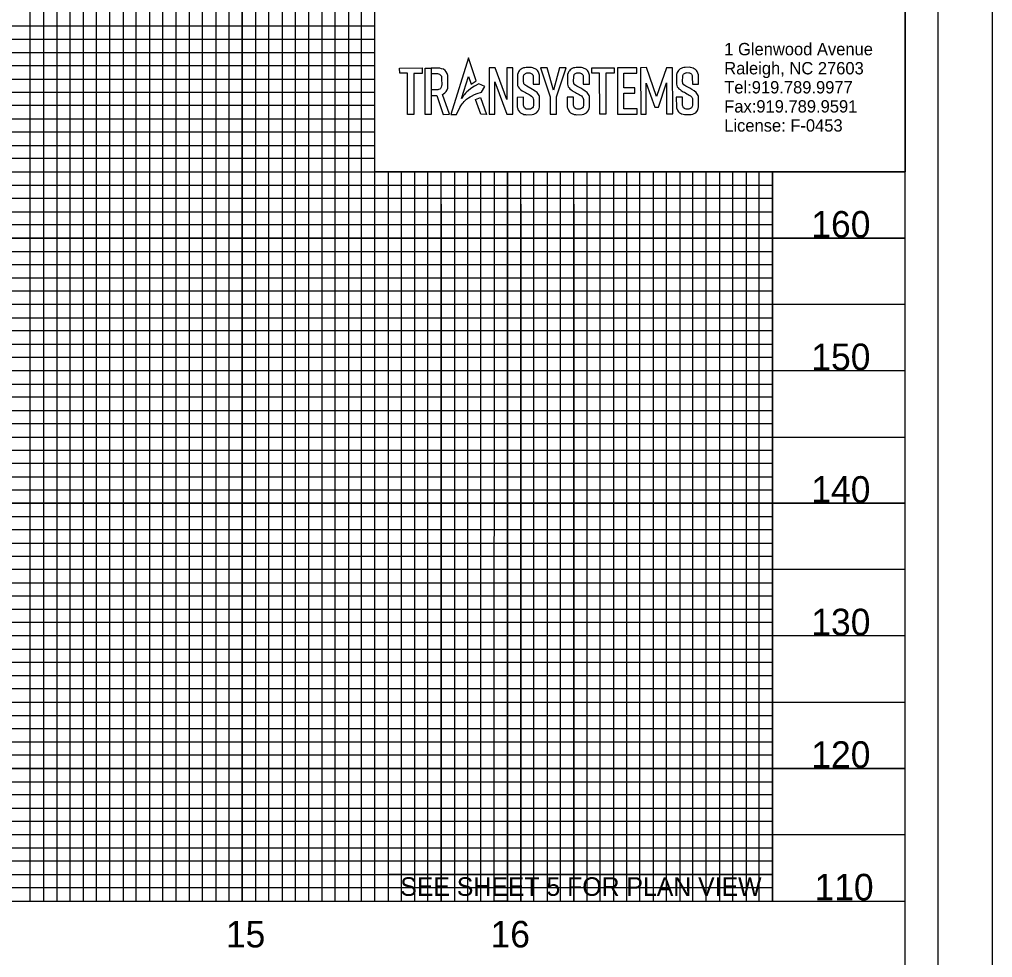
# Model space of a CAD drawing. Extents: x 1779926 to 1781626, y 618464 to 619564.
# Drawn here: x 1781258.9 to 1781626, y 619017.9 to 619371.7 of the extents above; entities that cross this region are included whole.
import ezdxf

# ---------------------------------------------------------------- set-up
doc = ezdxf.new("R2010")
doc.units = 0
for name, color, linetype in [('Default', 7, 'Continuous'), ('Exist Vertical Profile Horizontal Axis Label Major', 7, 'Continuous'), ('Exist Vertical Profile Vertical Axis Label', 7, 'Continuous'), ('Old_Level_2', 7, 'Continuous'), ('Old_Level_58', 7, 'Continuous'), ('Prop DSN Text', 7, 'Continuous'), ('Prop Grid Mask', 7, 'Continuous'), ('Sheet DOT Grid CELL', 7, 'Continuous'), ('Sheet Layout Profile Border Port 1', 7, 'Continuous'), ('Sheet Plot Border Inside CELL', 7, 'Continuous'), ('Sheet Plot Border Outside CELL', 7, 'Continuous'), ('Sheet Profile CELL', 7, 'Continuous'), ('Sheet Profile Grid Major CELL', 7, 'Continuous'), ('Sheet Profile Grid Middle CELL', 7, 'Continuous'), ('Sheet Profile Grid Minor CELL', 7, 'Continuous')]:
    doc.layers.add(name, color=color, linetype=linetype)

msp = doc.modelspace()

# ---------------------------------------------------------------- linework, layer by layer
at = {"layer": 'Default'}
for points in [[(1781428.25, 619357.23), (1781421.58, 619335.89), (1781423.81, 619335.9), (1781424.15, 619336.74), (1781424.72, 619337.9), (1781425.03, 619338.53), (1781425.41, 619339.07), (1781425.93, 619339.83), (1781426.26, 619340.3), (1781426.64, 619340.69), (1781427.02, 619341.08), (1781427.51, 619341.58), (1781427.92, 619341.85), (1781428.33, 619342.18), (1781428.89, 619342.5), (1781429.38, 619342.78), (1781430.6, 619343.35), (1781431.6, 619343.76), (1781433.24, 619344.32), (1781434.38, 619346.46), (1781432.2, 619347.42), (1781430.57, 619346.53), (1781429.19, 619345.63), (1781428.21, 619344.83), (1781427.69, 619344.41), (1781427.15, 619343.84), (1781426.62, 619343.27), (1781426.22, 619342.85), (1781425.84, 619342.2), (1781425.63, 619341.84), (1781428.26, 619350.22), (1781429.26, 619347.33), (1781431.16, 619348.58)], [(1781402.29, 619353.38), (1781410.75, 619353.39), (1781410.75, 619351.31), (1781407.64, 619351.31), (1781407.66, 619335.89), (1781405.31, 619335.89), (1781405.29, 619351.41), (1781402.32, 619351.41)], [(1781411.91, 619353.37), (1781414.22, 619353.38), (1781414.24, 619335.81), (1781411.92, 619335.81)], [(1781414.22, 619351.29), (1781416.61, 619351.29), (1781416.91, 619351.24), (1781417.32, 619351.08), (1781417.64, 619350.86), (1781417.87, 619350.59), (1781418.03, 619350.26), (1781418.15, 619350), (1781418.15, 619349.42), (1781418.16, 619346.93), (1781418.1, 619346.6), (1781418.01, 619346.16), (1781417.88, 619345.86), (1781417.68, 619345.6), (1781417.41, 619345.39), (1781416.99, 619345.24), (1781416.66, 619345.2), (1781416.34, 619345.15), (1781414.23, 619345.14), (1781414.24, 619343.03), (1781416.35, 619343.05), (1781418.72, 619335.88), (1781421.13, 619335.91), (1781418.48, 619343.45), (1781418.86, 619343.58), (1781419.4, 619343.98), (1781419.89, 619344.52), (1781420.23, 619345.15), (1781420.45, 619345.78), (1781420.43, 619345.97), (1781420.48, 619350.53), (1781420.27, 619351.28), (1781419.91, 619351.96), (1781419.5, 619352.43), (1781418.8, 619352.9), (1781418.12, 619353.13), (1781417.45, 619353.35), (1781417.04, 619353.35), (1781414.22, 619353.38)], [(1781436.02, 619353.41), (1781436.03, 619335.95), (1781438.27, 619335.95), (1781438.26, 619348.23), (1781442.71, 619335.93), (1781444.96, 619335.96), (1781444.94, 619353.46), (1781442.76, 619353.46), (1781442.78, 619341.48), (1781438.37, 619353.42)], [(1781452.72, 619347.24), (1781455.03, 619347.24), (1781455.02, 619350.72), (1781454.83, 619351.42), (1781454.55, 619352.01), (1781454.25, 619352.4), (1781453.88, 619352.76), (1781453.44, 619353.04), (1781453.01, 619353.21), (1781453.01, 619353.21), (1781452.55, 619353.41), (1781452.07, 619353.53), (1781451.75, 619353.61), (1781450, 619353.57), (1781449.47, 619353.48), (1781449.02, 619353.4), (1781448.55, 619353.16), (1781448.15, 619352.95), (1781447.76, 619352.67), (1781447.45, 619352.35), (1781447.2, 619351.99), (1781447.01, 619351.59), (1781446.75, 619350.9), (1781446.7, 619350.38), (1781446.7, 619347.21), (1781446.82, 619346.74), (1781447.05, 619346.24), (1781447.34, 619345.83), (1781447.63, 619345.52), (1781448.08, 619345.17), (1781448.54, 619344.83), (1781448.82, 619344.61), (1781449.3, 619344.38), (1781449.79, 619344.16), (1781450.18, 619343.9), (1781450.62, 619343.62), (1781451.15, 619343.35), (1781451.58, 619343.13), (1781452.01, 619342.82), (1781452.32, 619342.52), (1781452.57, 619342.28), (1781452.72, 619341.8), (1781452.82, 619341.5), (1781452.78, 619339.27), (1781452.62, 619338.78), (1781452.38, 619338.36), (1781452.05, 619338.07), (1781451.69, 619337.91), (1781451.35, 619337.84), (1781450.39, 619337.82), (1781450.07, 619337.91), (1781449.74, 619338.1), (1781449.41, 619338.3), (1781449.27, 619338.63), (1781449.13, 619338.97), (1781449.01, 619339.23), (1781448.98, 619342.35), (1781446.64, 619342.32), (1781446.68, 619338.61), (1781446.8, 619338.33), (1781447.07, 619337.46), (1781447.24, 619337.17), (1781447.5, 619336.85), (1781447.88, 619336.48), (1781448.18, 619336.29), (1781448.62, 619336.1), (1781448.78, 619336.04), (1781449.2, 619335.86), (1781449.74, 619335.8), (1781450.13, 619335.76), (1781452.27, 619335.82), (1781452.87, 619335.96), (1781453.69, 619336.33), (1781453.97, 619336.46), (1781454.6, 619337.25), (1781454.93, 619338.04), (1781455.08, 619338.75), (1781455.03, 619342.17), (1781455.02, 619342.64), (1781454.89, 619343.02), (1781454.7, 619343.37), (1781454.16, 619344.13), (1781453.45, 619344.69), (1781452.48, 619345.27), (1781451.73, 619345.71), (1781450.27, 619346.48), (1781449.52, 619347.04), (1781449.19, 619347.46), (1781449.11, 619347.74), (1781449.03, 619348.03), (1781449.08, 619350.46), (1781449.2, 619350.71), (1781449.33, 619350.97), (1781449.51, 619351.12), (1781449.74, 619351.32), (1781450, 619351.42), (1781450.25, 619351.53), (1781450.4, 619351.5), (1781450.42, 619351.58), (1781451.38, 619351.56), (1781451.65, 619351.45), (1781451.93, 619351.34), (1781452.21, 619351.23), (1781452.34, 619351.04), (1781452.52, 619350.76), (1781452.61, 619350.48), (1781452.71, 619350.21), (1781452.7, 619349.9)], [(1781457.99, 619353.42), (1781455.45, 619353.42), (1781459.07, 619342.54), (1781459.1, 619335.99), (1781461.49, 619336.01), (1781461.46, 619342.5), (1781465.12, 619353.46), (1781462.62, 619353.39), (1781460.31, 619345.05)], [(1781471.59, 619347.26), (1781473.9, 619347.26), (1781473.89, 619350.74), (1781473.7, 619351.44), (1781473.42, 619352.03), (1781473.12, 619352.42), (1781472.75, 619352.77), (1781472.31, 619353.06), (1781471.88, 619353.23), (1781471.88, 619353.23), (1781471.43, 619353.42), (1781470.94, 619353.55), (1781470.62, 619353.63), (1781468.87, 619353.59), (1781468.34, 619353.5), (1781467.89, 619353.42), (1781467.43, 619353.18), (1781467.02, 619352.97), (1781466.63, 619352.68), (1781466.32, 619352.37), (1781466.08, 619352.01), (1781465.88, 619351.61), (1781465.63, 619350.91), (1781465.58, 619350.4), (1781465.58, 619347.23), (1781465.69, 619346.75), (1781465.92, 619346.26), (1781466.21, 619345.85), (1781466.51, 619345.54), (1781466.96, 619345.19), (1781467.41, 619344.84), (1781467.69, 619344.62), (1781468.18, 619344.4), (1781468.66, 619344.17), (1781469.05, 619343.92), (1781469.49, 619343.63), (1781470.02, 619343.37), (1781470.45, 619343.15), (1781470.88, 619342.83), (1781471.19, 619342.54), (1781471.44, 619342.3), (1781471.59, 619341.82), (1781471.69, 619341.52), (1781471.65, 619339.28), (1781471.49, 619338.8), (1781471.25, 619338.38), (1781470.92, 619338.09), (1781470.56, 619337.93), (1781470.22, 619337.86), (1781469.26, 619337.84), (1781468.94, 619337.93), (1781468.61, 619338.12), (1781468.28, 619338.31), (1781468.14, 619338.65), (1781468, 619338.98), (1781467.88, 619339.25), (1781467.85, 619342.36), (1781465.51, 619342.34), (1781465.55, 619338.63), (1781465.67, 619338.34), (1781465.94, 619337.48), (1781466.12, 619337.19), (1781466.37, 619336.87), (1781466.75, 619336.5), (1781467.05, 619336.3), (1781467.49, 619336.12), (1781467.65, 619336.05), (1781468.08, 619335.87), (1781468.61, 619335.82), (1781469, 619335.78), (1781471.15, 619335.84), (1781471.74, 619335.98), (1781472.57, 619336.35), (1781472.85, 619336.48), (1781473.47, 619337.27), (1781473.8, 619338.05), (1781473.96, 619338.76), (1781473.9, 619342.19), (1781473.9, 619342.66), (1781473.76, 619343.03), (1781473.57, 619343.39), (1781473.03, 619344.15), (1781472.33, 619344.7), (1781471.35, 619345.28), (1781470.61, 619345.73), (1781469.14, 619346.49), (1781468.39, 619347.06), (1781468.06, 619347.48), (1781467.98, 619347.76), (1781467.91, 619348.05), (1781467.95, 619350.48), (1781468.08, 619350.73), (1781468.2, 619350.99), (1781468.38, 619351.14), (1781468.61, 619351.33), (1781468.87, 619351.44), (1781469.13, 619351.55), (1781469.27, 619351.52), (1781469.29, 619351.59), (1781470.25, 619351.58), (1781470.52, 619351.47), (1781470.8, 619351.36), (1781471.08, 619351.25), (1781471.21, 619351.06), (1781471.39, 619350.78), (1781471.49, 619350.5), (1781471.58, 619350.23), (1781471.57, 619349.92)], [(1781474.74, 619353.45), (1781483.21, 619353.45), (1781483.21, 619351.38), (1781480.1, 619351.38), (1781480.12, 619335.96), (1781477.77, 619335.95), (1781477.75, 619351.48), (1781474.78, 619351.48)], [(1781491.82, 619353.45), (1781484.43, 619353.45), (1781484.45, 619336.02), (1781491.92, 619336.03), (1781491.92, 619338), (1781486.87, 619337.99), (1781486.87, 619343.84), (1781491.08, 619343.84), (1781491.08, 619345.91), (1781486.83, 619345.91), (1781486.83, 619351.41), (1781491.84, 619351.41)], [(1781499.19, 619342.6), (1781495.38, 619353.53), (1781493.17, 619353.42), (1781493.25, 619335.96), (1781495.36, 619335.97), (1781495.31, 619347.65), (1781498.57, 619338.66), (1781499.92, 619338.63), (1781502.99, 619347.76), (1781503.03, 619336.04), (1781505.32, 619336.05), (1781505.25, 619353.47), (1781502.95, 619353.46)], [(1781512.72, 619347.3), (1781515.03, 619347.3), (1781515.03, 619350.77), (1781514.83, 619351.48), (1781514.55, 619352.07), (1781514.25, 619352.46), (1781513.88, 619352.81), (1781513.44, 619353.09), (1781513.02, 619353.27), (1781513.02, 619353.27), (1781512.56, 619353.46), (1781512.08, 619353.58), (1781511.76, 619353.66), (1781510.01, 619353.63), (1781509.48, 619353.54), (1781509.02, 619353.46), (1781508.56, 619353.22), (1781508.15, 619353.01), (1781507.76, 619352.72), (1781507.45, 619352.41), (1781507.21, 619352.04), (1781507.01, 619351.65), (1781506.76, 619350.95), (1781506.71, 619350.44), (1781506.71, 619347.27), (1781506.82, 619346.79), (1781507.05, 619346.3), (1781507.34, 619345.89), (1781507.64, 619345.58), (1781508.09, 619345.23), (1781508.54, 619344.88), (1781508.83, 619344.66), (1781509.31, 619344.44), (1781509.79, 619344.21), (1781510.18, 619343.96), (1781510.62, 619343.67), (1781511.15, 619343.41), (1781511.58, 619343.19), (1781512.01, 619342.87), (1781512.32, 619342.58), (1781512.57, 619342.34), (1781512.73, 619341.86), (1781512.82, 619341.56), (1781512.79, 619339.32), (1781512.62, 619338.84), (1781512.38, 619338.42), (1781512.05, 619338.13), (1781511.7, 619337.97), (1781511.36, 619337.9), (1781510.39, 619337.88), (1781510.07, 619337.97), (1781509.74, 619338.16), (1781509.41, 619338.35), (1781509.27, 619338.69), (1781509.13, 619339.02), (1781509.02, 619339.29), (1781508.98, 619342.4), (1781506.64, 619342.37), (1781506.69, 619338.66), (1781506.8, 619338.38), (1781507.07, 619337.52), (1781507.25, 619337.23), (1781507.5, 619336.91), (1781507.88, 619336.53), (1781508.19, 619336.34), (1781508.62, 619336.16), (1781508.78, 619336.09), (1781509.21, 619335.91), (1781509.74, 619335.86), (1781510.14, 619335.82), (1781512.28, 619335.87), (1781512.87, 619336.01), (1781513.7, 619336.39), (1781513.98, 619336.51), (1781514.6, 619337.31), (1781514.93, 619338.09), (1781515.09, 619338.8), (1781515.04, 619342.22), (1781515.03, 619342.7), (1781514.9, 619343.07), (1781514.71, 619343.43), (1781514.17, 619344.19), (1781513.46, 619344.74), (1781512.48, 619345.32), (1781511.74, 619345.77), (1781510.28, 619346.53), (1781509.52, 619347.09), (1781509.19, 619347.52), (1781509.12, 619347.8), (1781509.04, 619348.08), (1781509.08, 619350.51), (1781509.21, 619350.77), (1781509.33, 619351.02), (1781509.51, 619351.18), (1781509.74, 619351.37), (1781510, 619351.48), (1781510.26, 619351.59), (1781510.41, 619351.56), (1781510.42, 619351.63), (1781511.38, 619351.62), (1781511.66, 619351.51), (1781511.93, 619351.4), (1781512.21, 619351.29), (1781512.34, 619351.09), (1781512.53, 619350.82), (1781512.62, 619350.54), (1781512.71, 619350.26), (1781512.7, 619349.96)], [(1781430.86, 619341.52), (1781432.78, 619342.29), (1781435.04, 619335.85), (1781432.94, 619335.93)]]:
    msp.add_lwpolyline(points, close=True, dxfattribs=at)
at = {"layer": 'Old_Level_58'}
msp.add_lwpolyline([(1781392.96, 619378.14), (1781592.95, 619378.14), (1781592.95, 619314.19), (1781392.96, 619314.19)], close=True, dxfattribs=at)
at = {"layer": 'Prop Grid Mask'}
msp.add_lwpolyline([(1781542.96, 619049.19), (1781397.96, 619049.19), (1781397.96, 619039.19), (1781542.96, 619039.19)], close=True, dxfattribs=at)
at = {"layer": 'Sheet DOT Grid CELL'}
for p, q in [((1781292.96, 619039.19), (1781292.96, 619539.19)), ((1781342.96, 619039.19), (1781342.96, 619539.19)), ((1781392.96, 619039.19), (1781392.96, 619401.64)), ((1781392.91, 619339.19), (1780092.96, 619339.19)), ((1781442.96, 619039.19), (1781442.96, 619314.19)), ((1781492.96, 619039.19), (1781492.96, 619314.19)), ((1781542.96, 619039.19), (1781542.96, 619314.19)), ((1781592.96, 619289.19), (1780092.96, 619289.19)), ((1781592.96, 619239.19), (1780092.96, 619239.19)), ((1781592.96, 619189.19), (1780092.96, 619189.19)), ((1781592.96, 619139.19), (1780092.96, 619139.19)), ((1781592.96, 619089.19), (1780092.96, 619089.19))]:
    msp.add_line(p, q, dxfattribs=at)
at = {"layer": 'Sheet Layout Profile Border Port 1'}
msp.add_line((1781542.96, 619049.19), (1781542.96, 619099.19), dxfattribs=at)
for points in [[(1781542.96, 619099.19), (1781542.96, 619314.19), (1781392.91, 619314.19), (1781392.96, 619539.19), (1780142.96, 619539.19), (1780142.96, 619039.19), (1781542.96, 619039.19), (1781542.96, 619049.19)], [(1780142.96, 619378.14), (1780142.96, 619039.19), (1781542.96, 619039.19), (1781542.96, 619314.19)]]:
    msp.add_lwpolyline(points, dxfattribs=at)
at = {"layer": 'Sheet Plot Border Inside CELL'}
msp.add_lwpolyline([(1779938.96, 618486.64), (1781605.46, 618486.64), (1781605.46, 619541.74), (1779938.96, 619541.74)], close=True, dxfattribs=at)
at = {"layer": 'Sheet Plot Border Outside CELL'}
msp.add_lwpolyline([(1779925.96, 618464.19), (1781625.96, 618464.19), (1781625.96, 619564.19), (1779925.96, 619564.19)], close=True, dxfattribs=at)
at = {"layer": 'Sheet Profile CELL'}
msp.add_line((1780092.96, 619039.19), (1781592.96, 619039.19), dxfattribs=at)
msp.add_lwpolyline([(1781592.96, 619539.19), (1780092.96, 619539.19), (1780092.96, 618489.19), (1781592.96, 618489.19)], close=True, dxfattribs=at)
at = {"layer": 'Sheet Profile Grid Major CELL'}
for points in [[(1780842.96, 619039.19), (1780892.96, 619039.19), (1780892.96, 619539.19), (1780942.96, 619539.19), (1780942.96, 619039.19), (1780992.96, 619039.19), (1780992.96, 619539.19), (1781042.96, 619539.19), (1781042.96, 619039.19), (1781092.96, 619039.19), (1781092.96, 619539.19), (1781142.96, 619539.19), (1781142.96, 619039.19), (1781192.96, 619039.19), (1781192.96, 619539.19), (1781242.96, 619539.19), (1781242.96, 619039.19), (1781292.96, 619039.19), (1781292.96, 619539.19), (1781342.96, 619539.19), (1781342.96, 619039.19), (1781392.96, 619039.19), (1781392.96, 619539.19), (1781419.26, 619539.19)], [(1781542.96, 619314.19), (1781542.96, 619039.19), (1781592.96, 619039.19), (1781592.96, 619389.19)], [(1781392.96, 619339.19), (1780092.96, 619339.19), (1780092.96, 619289.19), (1781592.96, 619289.19)], [(1781442.96, 619314.19), (1781442.96, 619039.19), (1781492.96, 619039.19), (1781492.96, 619039.19), (1781492.96, 619314.19)], [(1781592.96, 619239.19), (1780092.96, 619239.19), (1780092.96, 619189.19), (1781592.96, 619189.19)], [(1781592.96, 619139.19), (1780092.96, 619139.19), (1780092.96, 619139.19), (1780092.96, 619089.19), (1781592.96, 619089.19)]]:
    msp.add_lwpolyline(points, dxfattribs=at)
at = {"layer": 'Sheet Profile Grid Middle CELL'}
for points in [[(1781217.96, 619539.19), (1781267.96, 619539.19), (1781267.96, 619039.19), (1781317.96, 619039.19), (1781317.96, 619539.19), (1781367.96, 619539.19), (1781367.96, 619039.19), (1781417.96, 619039.19), (1781417.96, 619314.19)], [(1781392.91, 619364.19), (1780092.96, 619364.19), (1780092.96, 619314.19), (1781417.96, 619314.19)], [(1781417.96, 619314.19), (1781592.96, 619314.19)], [(1781417.96, 619301.99), (1781417.96, 619039.19), (1781467.96, 619039.19), (1781467.96, 619314.19)], [(1781467.96, 619301.99), (1781467.96, 619039.19), (1781517.96, 619039.19), (1781517.96, 619314.19)], [(1781592.96, 619264.19), (1780092.96, 619264.19), (1780092.96, 619214.19), (1781592.96, 619214.19)], [(1781592.96, 619164.19), (1780092.96, 619164.19), (1780092.96, 619114.19), (1781592.96, 619114.19)], [(1781592.96, 619064.19), (1780092.96, 619064.19)]]:
    msp.add_lwpolyline(points, dxfattribs=at)
at = {"layer": 'Sheet Profile Grid Minor CELL'}
for p, q in [((1781392.91, 619354.19), (1780142.96, 619354.19)), ((1780142.96, 619349.19), (1781392.91, 619349.19)), ((1781392.91, 619329.19), (1780142.96, 619329.19)), ((1780142.96, 619324.19), (1781392.91, 619324.19)), ((1781542.96, 619304.19), (1780142.96, 619304.19)), ((1780142.96, 619299.19), (1781542.96, 619299.19)), ((1781542.96, 619294.19), (1780142.96, 619294.19)), ((1780142.96, 619284.19), (1781542.96, 619284.19)), ((1781542.96, 619279.19), (1780142.96, 619279.19)), ((1780142.96, 619274.19), (1781542.96, 619274.19)), ((1781542.96, 619269.19), (1780142.96, 619269.19)), ((1780142.96, 619259.19), (1781542.96, 619259.19)), ((1781542.96, 619254.19), (1780142.96, 619254.19)), ((1780142.96, 619249.19), (1781542.96, 619249.19)), ((1781542.96, 619244.19), (1780142.96, 619244.19)), ((1780142.96, 619234.19), (1781542.96, 619234.19)), ((1781542.96, 619229.19), (1780142.96, 619229.19)), ((1780142.96, 619224.19), (1781542.96, 619224.19)), ((1781542.96, 619219.19), (1780142.96, 619219.19)), ((1780142.96, 619209.19), (1781542.96, 619209.19)), ((1781542.96, 619204.19), (1780142.96, 619204.19)), ((1780142.96, 619199.19), (1781542.96, 619199.19)), ((1781542.96, 619194.19), (1780142.96, 619194.19)), ((1780142.96, 619184.19), (1781542.96, 619184.19)), ((1781542.96, 619179.19), (1780142.96, 619179.19)), ((1780142.96, 619174.19), (1781542.96, 619174.19)), ((1781542.96, 619169.19), (1780142.96, 619169.19)), ((1780142.96, 619159.19), (1781542.96, 619159.19)), ((1781542.96, 619154.19), (1780142.96, 619154.19)), ((1781542.96, 619149.19), (1780142.96, 619149.19)), ((1781542.96, 619144.19), (1780142.96, 619144.19)), ((1780142.96, 619134.19), (1781542.96, 619134.19)), ((1781542.96, 619129.19), (1780142.96, 619129.19)), ((1780142.96, 619124.19), (1781542.96, 619124.19)), ((1781542.96, 619119.19), (1780142.96, 619119.19)), ((1780142.96, 619109.19), (1781542.96, 619109.19)), ((1781542.96, 619104.19), (1780142.96, 619104.19)), ((1780142.96, 619099.19), (1781542.96, 619099.19)), ((1781542.96, 619094.19), (1780142.96, 619094.19)), ((1780142.96, 619084.19), (1781542.96, 619084.19)), ((1781542.96, 619079.19), (1780142.96, 619079.19)), ((1780142.96, 619074.19), (1781542.96, 619074.19)), ((1781542.96, 619069.19), (1780142.96, 619069.19)), ((1780142.96, 619059.19), (1781542.96, 619059.19)), ((1781542.96, 619054.19), (1780142.96, 619054.19)), ((1780142.96, 619049.19), (1781542.96, 619049.19))]:
    msp.add_line(p, q, dxfattribs=at)
for points in [[(1781257.96, 619039.19), (1781262.96, 619039.19), (1781262.96, 619539.19), (1781272.96, 619539.19), (1781272.96, 619039.19), (1781277.96, 619039.19), (1781277.96, 619539.19), (1781282.96, 619539.19), (1781282.96, 619039.19)], [(1781282.96, 619039.19), (1781287.96, 619039.19), (1781287.96, 619539.19)], [(1781297.96, 619539.19), (1781297.96, 619039.19), (1781302.96, 619039.19), (1781302.96, 619539.19)], [(1781307.96, 619539.19), (1781307.96, 619039.19), (1781312.96, 619039.19), (1781312.96, 619539.19)], [(1781322.96, 619539.19), (1781322.96, 619039.19), (1781327.96, 619039.19), (1781327.96, 619539.19)], [(1781332.96, 619539.19), (1781332.96, 619039.19), (1781337.96, 619039.19), (1781337.96, 619539.19)], [(1781347.96, 619539.19), (1781347.96, 619039.19), (1781352.96, 619039.19), (1781352.96, 619539.19)], [(1781357.96, 619539.19), (1781357.96, 619039.19), (1781362.96, 619039.19), (1781362.96, 619539.19)], [(1781372.96, 619539.19), (1781372.96, 619039.19), (1781377.96, 619039.19), (1781377.96, 619539.19)], [(1781382.96, 619539.19), (1781382.96, 619039.19), (1781387.96, 619039.19), (1781387.96, 619539.19)], [(1781392.91, 619369.19), (1780142.96, 619369.19), (1780142.96, 619359.19), (1781392.91, 619359.19)], [(1781392.91, 619344.19), (1780142.96, 619344.19), (1780142.96, 619334.19), (1781392.91, 619334.19)], [(1781392.91, 619319.19), (1780142.96, 619319.19), (1780142.96, 619309.19), (1781542.96, 619309.19)], [(1781397.96, 619314.19), (1781397.96, 619039.19), (1781402.96, 619039.19), (1781402.96, 619314.19)], [(1781407.96, 619314.19), (1781407.96, 619039.19), (1781412.96, 619039.19), (1781412.96, 619314.19)], [(1781422.96, 619314.19), (1781422.96, 619039.19), (1781422.96, 619039.19), (1781427.96, 619039.19), (1781432.96, 619039.19), (1781432.96, 619314.19)], [(1781427.96, 619314.19), (1781427.96, 619039.19)], [(1781437.94, 619314.19), (1781437.86, 619039.24), (1781442.86, 619039.24), (1781447.96, 619039.19), (1781447.96, 619314.19)], [(1781447.96, 619301.99), (1781447.96, 619039.19), (1781452.96, 619039.19), (1781452.96, 619314.19)], [(1781457.96, 619314.19), (1781457.96, 619039.19), (1781462.96, 619039.19), (1781462.96, 619314.19)], [(1781472.96, 619314.19), (1781472.96, 619039.19), (1781477.96, 619039.19), (1781477.96, 619314.19)], [(1781482.96, 619314.19), (1781482.96, 619039.19), (1781487.96, 619039.19), (1781487.96, 619314.19)], [(1781497.96, 619314.19), (1781497.96, 619039.19), (1781502.96, 619039.19), (1781502.96, 619314.19)], [(1781507.96, 619314.19), (1781507.96, 619039.19), (1781512.96, 619039.19), (1781512.96, 619314.19)], [(1781522.96, 619314.19), (1781522.96, 619039.19), (1781527.96, 619039.19), (1781527.96, 619314.19)], [(1781532.96, 619314.19), (1781532.96, 619039.19), (1781537.96, 619039.19), (1781537.96, 619314.19)], [(1781542.96, 619044.19), (1780142.96, 619044.19)]]:
    msp.add_lwpolyline(points, dxfattribs=at)

# ---------------------------------------------------------------- texts
at = {"layer": 'Exist Vertical Profile Horizontal Axis Label Major'}
for s, p in [('15', (1781336.75, 619021.69)), ('16', (1781436.58, 619021.69))]:
    msp.add_text(s, height=10, dxfattribs=at).set_placement(p)
at = {"layer": 'Exist Vertical Profile Vertical Axis Label'}
for s, p in [('160', (1781557.59, 619289.44)), ('150', (1781557.59, 619239.44)), ('140', (1781557.59, 619189.44)), ('130', (1781557.59, 619139.44)), ('120', (1781557.59, 619089.44)), ('110', (1781558.79, 619039.44))]:
    msp.add_text(s, height=10, dxfattribs=at).set_placement(p)
at = {"layer": 'Old_Level_2'}
for s, p in [('1 Glenwood Avenue', (1781524.75, 619358.18)), ('Raleigh, NC 27603', (1781524.75, 619350.98)), ('Tel:919.789.9977 ', (1781524.75, 619343.79)), ('Fax:919.789.9591', (1781524.75, 619336.59)), ('License: F-0453', (1781524.75, 619329.39))]:
    msp.add_text(s, height=4.6576, rotation=360, dxfattribs=at).set_placement(p)
at = {"layer": 'Prop DSN Text'}
msp.add_text('SEE SHEET 5 FOR PLAN VIEW', height=7, dxfattribs=at).set_placement((1781402.54, 619041.14))

doc.saveas('drawing.dxf')
